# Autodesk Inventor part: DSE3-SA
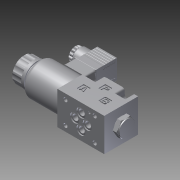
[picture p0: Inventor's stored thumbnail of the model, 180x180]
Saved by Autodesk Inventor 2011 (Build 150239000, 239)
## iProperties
Created: 2012-01
Part Number: DSE3-SA
Document SubType Name: Modeling
Designer: khramov
Density: 1 g/cm^3
Author: khramov
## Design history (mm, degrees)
node "Твердое тело1"
derived "DSE3_C01SA_11N_D12K1.iam"
node "0144338.ipt:1"
node "190293_.ipt:1"
node "026977.ipt:1"
node "0119425_.ipt:1"
sketch "0670792_.ipt:1"
node "0128117.ipt:1"
sketch "3001630001_.ipt:1"
